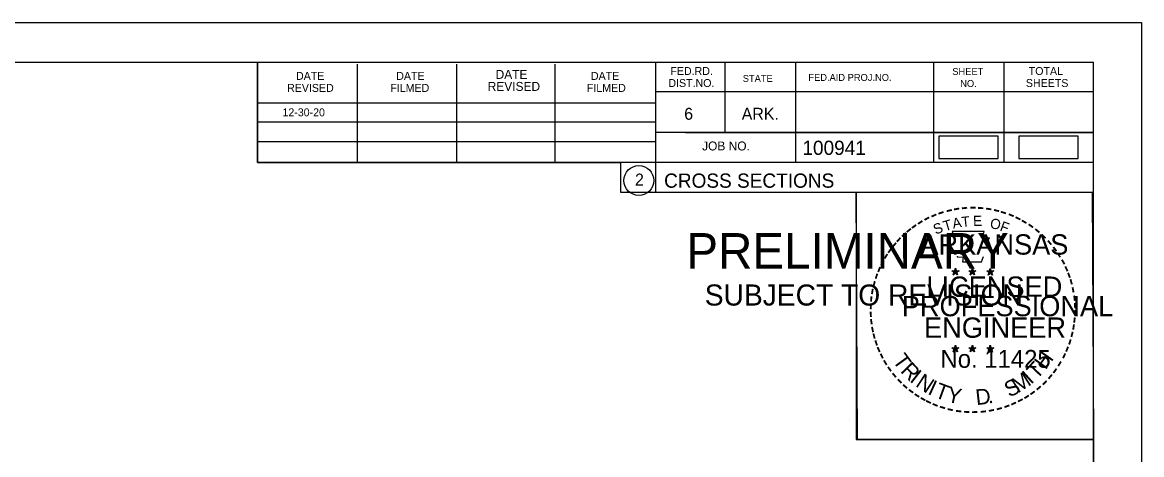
# Model space of a CAD drawing. Extents: x 1370538 to 1372872, y 376220 to 381127.
# Drawn here: x 1370761.4 to 1370871.5, y 376604.6 to 376647.1 of the extents above; entities that cross this region are included whole.
import ezdxf

# ---------------------------------------------------------------- set-up
doc = ezdxf.new("R2010")
doc.units = 0
for name, color, linetype in [('Default', 7, 'Continuous'), ('R_Border Notes', 7, 'Continuous'), ('R_No Plot', 7, 'Continuous'), ('T_Indications', 7, 'Continuous'), ('T_Notes', 7, 'Continuous')]:
    doc.layers.add(name, color=color, linetype=linetype)

msp = doc.modelspace()

# ---------------------------------------------------------------- linework, layer by layer
at = {"layer": 'Default'}
for points in [[(1370851.6, 376633.71), (1370857.43, 376633.71), (1370857.43, 376635.9), (1370851.6, 376635.9)], [(1370859.47, 376633.71), (1370865.3, 376633.71), (1370865.3, 376635.9), (1370859.47, 376635.9)]]:
    msp.add_lwpolyline(points, close=True, dxfattribs=at)
at = {"layer": 'R_Border Notes'}
for p, q in [((1370550.61, 376643.21), (1370866.79, 376643.21)), ((1370784.53, 376633.33), (1370784.53, 376643.21)), ((1370794.39, 376633.33), (1370794.39, 376643.01)), ((1370804.15, 376633.33), (1370804.15, 376643.01)), ((1370813.83, 376633.33), (1370813.83, 376643.01)), ((1370823.69, 376643.21), (1370823.69, 376630.41)), ((1370830.53, 376643.21), (1370830.53, 376636.27)), ((1370837.47, 376643.21), (1370837.47, 376633.33)), ((1370851.05, 376643.21), (1370851.05, 376633.33)), ((1370857.99, 376643.21), (1370857.99, 376633.33)), ((1370866.79, 376437.75), (1370866.79, 376643.21)), ((1370866.79, 376640.27), (1370823.69, 376640.27)), ((1370866.79, 376640.29), (1370866.79, 376640.29)), ((1370784.53, 376639.19), (1370823.69, 376639.19)), ((1370784.53, 376637.33), (1370823.69, 376637.33)), ((1370866.79, 376636.27), (1370823.69, 376636.27)), ((1370826.65, 376636.27), (1370866.79, 376636.27)), ((1370784.53, 376633.33), (1370784.53, 376635.39)), ((1370784.53, 376635.39), (1370823.69, 376635.39)), ((1370866.79, 376633.33), (1370784.53, 376633.33)), ((1370823.69, 376630.41), (1370866.79, 376630.41))]:
    msp.add_line(p, q, dxfattribs=at)
msp.add_circle((1370822.07, 376631.55), 1.47, dxfattribs=at)
at = {"layer": 'R_No Plot'}
for p, q in [((1370538.21, 376647.11), (1370871.54, 376647.11)), ((1370842.82, 376607.96), (1370842.82, 376607.96))]:
    msp.add_line(p, q, dxfattribs=at)
for points in [[(1370538.2, 376647.11), (1370871.54, 376647.11), (1370871.54, 376433.77), (1370538.2, 376433.77)], [(1370784.53, 376643.21), (1370784.53, 376633.33), (1370820.26, 376633.33), (1370820.26, 376630.41), (1370843.46, 376630.41), (1370843.46, 376606.08), (1370866.79, 376606.08), (1370866.79, 376437.75), (1370550.61, 376437.75), (1370550.61, 376643.21)], [(1370843.46, 376630.41), (1370866.67, 376630.41), (1370866.79, 376606.08), (1370843.58, 376606.08)]]:
    msp.add_lwpolyline(points, close=True, dxfattribs=at)
at = {"layer": 'T_Indications'}
for p, q in [((1370852.87, 376622.67), (1370853.22, 376622.56)), ((1370852.87, 376622.67), (1370853.12, 376622.62)), ((1370852.87, 376622.67), (1370853.11, 376622.55)), ((1370853, 376622.26), (1370853.22, 376622.56)), ((1370853, 376622.26), (1370853.13, 376622.5)), ((1370853, 376622.26), (1370853.22, 376622.48)), ((1370853.22, 376622.92), (1370853.18, 376622.67)), ((1370853.22, 376622.56), (1370853.22, 376622.92)), ((1370853.22, 376622.92), (1370853.27, 376622.67)), ((1370853.57, 376622.67), (1370853.22, 376622.56)), ((1370853.43, 376622.26), (1370853.22, 376622.56)), ((1370853.43, 376622.26), (1370853.22, 376622.47)), ((1370853.57, 376622.67), (1370853.28, 376622.62)), ((1370853.43, 376622.26), (1370853.3, 376622.55)), ((1370853.57, 376622.67), (1370853.36, 376622.57)), ((1370854.54, 376622.67), (1370854.89, 376622.56)), ((1370854.54, 376622.67), (1370854.79, 376622.62)), ((1370854.54, 376622.67), (1370854.78, 376622.55)), ((1370854.67, 376622.26), (1370854.89, 376622.56)), ((1370854.67, 376622.26), (1370854.8, 376622.5)), ((1370854.67, 376622.26), (1370854.89, 376622.48)), ((1370854.89, 376622.92), (1370854.85, 376622.67)), ((1370854.89, 376622.56), (1370854.89, 376622.92)), ((1370854.89, 376622.92), (1370854.94, 376622.67)), ((1370855.24, 376622.67), (1370854.89, 376622.56)), ((1370855.1, 376622.26), (1370854.89, 376622.56)), ((1370855.1, 376622.26), (1370854.89, 376622.47)), ((1370855.24, 376622.67), (1370854.95, 376622.62)), ((1370855.1, 376622.26), (1370854.97, 376622.55)), ((1370855.24, 376622.67), (1370855.03, 376622.57)), ((1370856.31, 376622.66), (1370856.65, 376622.54)), ((1370856.31, 376622.66), (1370856.56, 376622.61)), ((1370856.31, 376622.66), (1370856.54, 376622.53)), ((1370856.44, 376622.25), (1370856.65, 376622.54)), ((1370856.44, 376622.25), (1370856.56, 376622.49)), ((1370856.44, 376622.25), (1370856.65, 376622.46)), ((1370856.65, 376622.91), (1370856.61, 376622.66)), ((1370856.65, 376622.54), (1370856.65, 376622.91)), ((1370856.65, 376622.91), (1370856.7, 376622.66)), ((1370857, 376622.66), (1370856.65, 376622.54)), ((1370856.87, 376622.25), (1370856.65, 376622.54)), ((1370856.87, 376622.25), (1370856.65, 376622.46)), ((1370857, 376622.66), (1370856.72, 376622.61)), ((1370856.87, 376622.25), (1370856.73, 376622.54)), ((1370857, 376622.66), (1370856.8, 376622.55)), ((1370852.87, 376615.09), (1370853.22, 376614.98)), ((1370852.87, 376615.09), (1370853.12, 376615.05)), ((1370852.87, 376615.09), (1370853.1, 376614.97)), ((1370853, 376614.69), (1370853.22, 376614.98)), ((1370853, 376614.69), (1370853.13, 376614.93)), ((1370853, 376614.69), (1370853.21, 376614.9)), ((1370853.22, 376615.35), (1370853.18, 376615.1)), ((1370853.43, 376614.69), (1370853.21, 376614.9)), ((1370853.22, 376614.98), (1370853.22, 376615.35)), ((1370853.22, 376615.35), (1370853.27, 376615.1)), ((1370853.56, 376615.09), (1370853.22, 376614.98)), ((1370853.43, 376614.69), (1370853.22, 376614.98)), ((1370853.56, 376615.09), (1370853.28, 376615.05)), ((1370853.43, 376614.69), (1370853.29, 376614.98)), ((1370853.56, 376615.09), (1370853.36, 376614.99)), ((1370854.54, 376615.09), (1370854.89, 376614.98)), ((1370854.54, 376615.09), (1370854.79, 376615.05)), ((1370854.54, 376615.09), (1370854.77, 376614.97)), ((1370854.67, 376614.69), (1370854.89, 376614.98)), ((1370854.67, 376614.69), (1370854.8, 376614.93)), ((1370854.67, 376614.69), (1370854.88, 376614.9)), ((1370854.89, 376615.35), (1370854.84, 376615.1)), ((1370855.1, 376614.69), (1370854.88, 376614.9)), ((1370854.89, 376614.98), (1370854.89, 376615.35)), ((1370854.89, 376615.35), (1370854.93, 376615.1)), ((1370855.23, 376615.09), (1370854.89, 376614.98)), ((1370855.1, 376614.69), (1370854.89, 376614.98)), ((1370855.23, 376615.09), (1370854.95, 376615.05)), ((1370855.1, 376614.69), (1370854.96, 376614.98)), ((1370855.23, 376615.09), (1370855.03, 376614.99)), ((1370856.3, 376615.08), (1370856.65, 376614.97)), ((1370856.3, 376615.08), (1370856.56, 376615.04)), ((1370856.3, 376615.08), (1370856.54, 376614.96)), ((1370856.44, 376614.68), (1370856.65, 376614.97)), ((1370856.44, 376614.68), (1370856.56, 376614.92)), ((1370856.44, 376614.68), (1370856.65, 376614.89)), ((1370856.65, 376615.34), (1370856.61, 376615.09)), ((1370856.65, 376614.97), (1370856.65, 376615.34)), ((1370856.65, 376615.34), (1370856.7, 376615.09)), ((1370857, 376615.08), (1370856.65, 376614.97)), ((1370856.87, 376614.68), (1370856.65, 376614.97)), ((1370856.87, 376614.68), (1370856.65, 376614.89)), ((1370857, 376615.08), (1370856.71, 376615.04)), ((1370856.87, 376614.68), (1370856.73, 376614.97)), ((1370857, 376615.08), (1370856.8, 376614.98))]:
    msp.add_line(p, q, dxfattribs=at)
for points in [[(1370852.91, 376626.55), (1370853.18, 376625.72)], [(1370856.42, 376625.62), (1370856.57, 376625.91), (1370855.88, 376625.88), (1370856.03, 376626.55), (1370852.91, 376626.55)], [(1370853.4, 376624.12), (1370853.4, 376624.04), (1370853.97, 376624.02), (1370853.91, 376623.54), (1370855.78, 376623.54), (1370855.98, 376624.08)], [(1370853.22, 376622.92), (1370853.43, 376622.26), (1370852.87, 376622.67), (1370853.57, 376622.67), (1370853, 376622.26), (1370853.22, 376622.92)], [(1370854.89, 376622.92), (1370855.1, 376622.26), (1370854.54, 376622.67), (1370855.24, 376622.67), (1370854.67, 376622.26), (1370854.89, 376622.92)], [(1370856.65, 376622.91), (1370856.87, 376622.25), (1370856.31, 376622.66), (1370857, 376622.66), (1370856.44, 376622.25), (1370856.65, 376622.91)], [(1370853.22, 376615.35), (1370853.43, 376614.69), (1370852.87, 376615.09), (1370853.56, 376615.09), (1370853, 376614.69), (1370853.22, 376615.35)], [(1370854.89, 376615.35), (1370855.1, 376614.69), (1370854.54, 376615.09), (1370855.23, 376615.09), (1370854.67, 376614.69), (1370854.89, 376615.35)], [(1370856.65, 376615.34), (1370856.87, 376614.68), (1370856.3, 376615.08), (1370857, 376615.08), (1370856.44, 376614.68), (1370856.65, 376615.34)]]:
    msp.add_lwpolyline(points, dxfattribs=at)
for centre, radius in [((1370853.22, 376622.56), 0.172), ((1370853.22, 376622.56), 0.145), ((1370853.22, 376622.56), 0.116), ((1370853.22, 376622.56), 0.0991), ((1370853.22, 376622.56), 0.0747), ((1370853.22, 376622.56), 0.0495), ((1370853.22, 376622.56), 0.0296), ((1370854.89, 376622.56), 0.172), ((1370854.89, 376622.56), 0.145), ((1370854.89, 376622.56), 0.116), ((1370854.89, 376622.56), 0.0991), ((1370854.89, 376622.56), 0.0747), ((1370854.89, 376622.56), 0.0495), ((1370854.89, 376622.56), 0.0296), ((1370856.65, 376622.54), 0.172), ((1370856.65, 376622.54), 0.145), ((1370856.65, 376622.54), 0.116), ((1370856.65, 376622.54), 0.0991), ((1370856.65, 376622.54), 0.0747), ((1370856.65, 376622.54), 0.0495), ((1370856.65, 376622.54), 0.0296), ((1370853.22, 376614.98), 0.172), ((1370853.22, 376614.98), 0.145), ((1370853.22, 376614.98), 0.116), ((1370853.22, 376614.98), 0.0991), ((1370853.22, 376614.98), 0.0747), ((1370853.22, 376614.98), 0.0495), ((1370853.22, 376614.98), 0.0296), ((1370854.88, 376614.98), 0.172), ((1370854.88, 376614.98), 0.145), ((1370854.88, 376614.98), 0.116), ((1370854.88, 376614.98), 0.0991), ((1370854.88, 376614.98), 0.0747), ((1370854.88, 376614.98), 0.0495), ((1370854.88, 376614.98), 0.0296), ((1370856.65, 376614.97), 0.172), ((1370856.65, 376614.97), 0.145), ((1370856.65, 376614.97), 0.116), ((1370856.65, 376614.97), 0.0991), ((1370856.65, 376614.97), 0.0747), ((1370856.65, 376614.97), 0.0495), ((1370856.65, 376614.97), 0.0296)]:
    msp.add_circle(centre, radius, dxfattribs=at)

# ---------------------------------------------------------------- texts
at = {"layer": 'R_Border Notes'}
for s, height, p in [('DATE', 0.879, (1370807.97, 376641.55)), ('FED.RD.', 0.782, (1370825.17, 376641.93)), ('SHEET', 0.684, (1370852.91, 376641.93)), ('TOTAL', 0.782, (1370860.43, 376641.93)), ('DATE', 0.782, (1370788.33, 376641.45)), ('DATE', 0.782, (1370798.19, 376641.45)), ('REVISED', 0.879, (1370807.19, 376640.37)), ('DATE', 0.782, (1370817.35, 376641.45)), ('DIST.NO.', 0.782, (1370824.97, 376640.75)), ('STATE', 0.684, (1370832.29, 376641.25)), ('FED.AID PROJ.NO.', 0.684, (1370838.75, 376641.35)), ('NO.', 0.684, (1370853.69, 376640.75)), ('SHEETS', 0.782, (1370860.15, 376640.75)), ('REVISED', 0.782, (1370787.45, 376640.27)), ('FILMED', 0.782, (1370797.61, 376640.27)), ('FILMED', 0.782, (1370816.95, 376640.27)), ('6', 1.17, (1370826.53, 376637.53)), ('ARK.', 1.172, (1370832.19, 376637.53)), ('JOB NO.', 0.879, (1370828.29, 376634.51)), ('100941', 1.4, (1370838.16, 376634.07)), ('2', 1.17, (1370821.69, 376631.06)), ('CROSS SECTIONS', 1.4, (1370824.55, 376630.84))]:
    msp.add_text(s, height=height, rotation=360, dxfattribs=at).set_placement(p)
msp.add_text('12-30-20', height=0.78, dxfattribs=at).set_placement((1370787, 376637.87))
at = {"layer": 'T_Indications'}
for s, height, rotation, p in [('-', 1.6, 28.7918, (1370850.39, 376627.09)), ('-', 1.6, 24.3072, (1370851.03, 376627.4)), ('-', 1.6, 19.1761, (1370851.66, 376627.67)), ('-', 1.6, 13.6301, (1370852.41, 376627.91)), ('-', 1.6, 10.2193, (1370853.09, 376628.08)), ('T', 1, 6.0228, (1370853.86, 376626.97)), ('-', 1.6, 5.8968, (1370853.82, 376628.19)), ('-', 1.6, 0.1862, (1370854.59, 376628.26)), ('E', 1, 0.8323, (1370854.96, 376627.08)), ('-', 1.6, 357.743, (1370855.31, 376628.24)), ('-', 1.6, 352.1617, (1370856.06, 376628.19)), ('-', 1.6, 347.2049, (1370856.78, 376628.07)), ('-', 1.6, 342.3362, (1370857.41, 376627.92)), ('-', 1.6, 337.8551, (1370858.15, 376627.7)), ('-', 1.6, 334.1211, (1370858.78, 376627.43)), ('-', 1.6, 38.9507, (1370848.74, 376625.94)), ('-', 1.6, 36.2317, (1370849.22, 376626.32)), ('-', 1.6, 34.0636, (1370849.8, 376626.72)), ('S', 1, 21.594, (1370851.27, 376626.22)), ('T', 1, 16.4036, (1370852.18, 376626.55)), ('A', 1, 11.2132, (1370853.01, 376626.81)), ('O', 1, 350.4515, (1370856.57, 376626.87)), ('F', 1, 340.0707, (1370857.52, 376626.64)), ('-', 1.6, 329.6409, (1370859.36, 376627.14)), ('-', 1.6, 325.8627, (1370860, 376626.78)), ('-', 1.6, 320.5297, (1370860.61, 376626.36)), ('-', 1.6, 48.423, (1370847.86, 376625.05)), ('-', 1.6, 42.9622, (1370848.31, 376625.53)), ('ARKANSAS', 2, 360, (1370849.77, 376624.26)), ('-', 1.6, 315.5786, (1370861.21, 376625.87)), ('-', 1.6, 54.2325, (1370847.05, 376624)), ('-', 1.6, 50.6142, (1370847.46, 376624.56)), ('-', 1.6, 309.8797, (1370861.78, 376625.32)), ('-', 1.6, 306.6522, (1370862.3, 376624.72)), ('-', 1.6, 62.8713, (1370846.41, 376622.85)), ('-', 1.6, 58.0706, (1370846.72, 376623.47)), ('-', 1.4, 303.6753, (1370862.79, 376624.15)), ('-', 1.6, 299.6684, (1370863.11, 376623.54)), ('-', 1.6, 72.3945, (1370845.93, 376621.61)), ('-', 1.6, 67.7743, (1370846.15, 376622.24)), ('DWB', 0.01, 360, (1370853.21, 376622.55)), ('DWB', 0.01, 360, (1370854.88, 376622.55)), ('DWB', 0.01, 360, (1370856.64, 376622.54)), ('-', 1.6, 294.6628, (1370863.43, 376622.93)), ('-', 1.6, 290.5728, (1370863.69, 376622.35)), ('-', 1.6, 75.461, (1370845.73, 376620.9)), ('LICENSED', 2, 360, (1370850.36, 376620.11)), ('-', 1.6, 285.1233, (1370863.92, 376621.77)), ('-', 1.6, 81.2013, (1370845.6, 376620.19)), ('PROFESSIONAL', 2, 360, (1370847.94, 376618.2)), ('-', 1.6, 280.5493, (1370864.12, 376621.03)), ('-', 1.6, 276.5962, (1370864.28, 376620.26)), ('-', 1.6, 89.0622, (1370845.5, 376618.79)), ('-', 1.6, 85.1863, (1370845.52, 376619.5)), ('-', 1.6, 274.3301, (1370864.34, 376619.54)), ('-', 1.6, 94.1959, (1370845.53, 376618.07)), ('ENGINEER', 2, 360, (1370850.13, 376616.08)), ('-', 1.6, 263.5172, (1370864.36, 376618.24)), ('-', 1.6, 269.9407, (1370864.38, 376618.91)), ('-', 1.6, 98.9479, (1370845.61, 376617.4)), ('-', 1.6, 101.7149, (1370845.74, 376616.67)), ('-', 1.6, 260.9953, (1370864.29, 376617.59)), ('-', 1.6, 105.4578, (1370845.9, 376616.07)), ('-', 1.6, 109.0874, (1370846.12, 376615.44)), ('-', 1.6, 252.8681, (1370864, 376616.19)), ('-', 1.6, 255.7626, (1370864.18, 376616.91)), ('-', 1.6, 114.0643, (1370846.37, 376614.85)), ('No. 11425', 1.757, 360, (1370851.75, 376613.13)), ('DWB', 0.01, 360, (1370853.2, 376614.98)), ('DWB', 0.01, 360, (1370854.87, 376614.98)), ('DWB', 0.01, 360, (1370856.64, 376614.97)), ('H', 1.54, 54.6088, (1370862.1, 376612.86)), ('-', 1.6, 247.8887, (1370863.77, 376615.52)), ('-', 1.6, 115.7289, (1370846.68, 376614.23)), ('-', 1.6, 120.4471, (1370847.03, 376613.64)), ('T', 1.54, 306.0406, (1370846.98, 376613.82)), ('R', 1.54, 314.005, (1370847.74, 376612.77)), ('T', 1.54, 46.6444, (1370861.21, 376611.91)), ('-', 1.6, 239.0712, (1370863.12, 376614.14)), ('-', 1.6, 244.6197, (1370863.51, 376614.89)), ('-', 1.6, 125.8934, (1370847.44, 376613.08)), ('-', 1.6, 130.7181, (1370847.9, 376612.53)), ('I', 1.54, 321.9694, (1370848.64, 376611.84)), ('N', 1.54, 326.5002, (1370849.21, 376611.37)), ('M', 1.54, 32.6563, (1370859.36, 376610.59)), ('I', 1.54, 42.1136, (1370860.64, 376611.44)), ('-', 1.6, 231.2538, (1370862.29, 376612.92)), ('-', 1.6, 233.8452, (1370862.72, 376613.48)), ('-', 1.6, 134.2238, (1370848.42, 376611.99)), ('-', 1.6, 138.9338, (1370848.94, 376611.52)), ('I', 1.54, 335.3603, (1370850.41, 376610.58)), ('T', 1.54, 339.8912, (1370851.08, 376610.26)), ('S', 1.54, 26.9312, (1370858.52, 376610.18)), ('-', 1.6, 225.7653, (1370861.81, 376612.35)), ('-', 1.6, 144.6463, (1370849.5, 376611.12)), ('-', 1.6, 148.0898, (1370850.06, 376610.74)), ('Y', 1.54, 347.8556, (1370852.29, 376609.81)), ('D', 1.54, 6.3969, (1370855.28, 376609.45)), ('-', 1.6, 212.2491, (1370860.2, 376610.98)), ('-', 1.6, 215.7363, (1370860.74, 376611.37)), ('-', 1.6, 221.0851, (1370861.28, 376611.84)), ('-', 1.6, 151.5704, (1370850.64, 376610.42)), ('-', 1.6, 154.6002, (1370851.16, 376610.17)), ('-', 1.6, 158.5612, (1370851.78, 376609.92)), ('-', 1.6, 162.7983, (1370852.47, 376609.71)), ('.', 1.54, 13.7642, (1370856.47, 376609.58)), ('-', 1.6, 195.4743, (1370857.72, 376609.8)), ('-', 1.6, 200.7184, (1370858.4, 376610.05)), ('-', 1.6, 204.2516, (1370859.02, 376610.32)), ('-', 1.6, 207.3568, (1370859.64, 376610.64)), ('-', 1.6, 167.5555, (1370853.19, 376609.54)), ('-', 1.6, 173.1155, (1370853.96, 376609.43)), ('-', 1.6, 176.5183, (1370854.71, 376609.38)), ('-', 1.6, 181.5918, (1370855.45, 376609.4)), ('-', 1.6, 185.8167, (1370856.26, 376609.47)), ('-', 1.6, 191.2858, (1370856.99, 376609.61))]:
    msp.add_text(s, height=height, rotation=rotation, dxfattribs=at).set_placement(p)
at = {"layer": 'T_Notes'}
for s, height, p in [('PRELIMINARY', 3.5, (1370826.74, 376622.88)), ('DWB', 0.01, (1370827.48, 376624.72)), ('SUBJECT TO REVISION', 2.0751, (1370828.55, 376619.25))]:
    msp.add_text(s, height=height, rotation=360, dxfattribs=at).set_placement(p)

doc.saveas('drawing.dxf')
